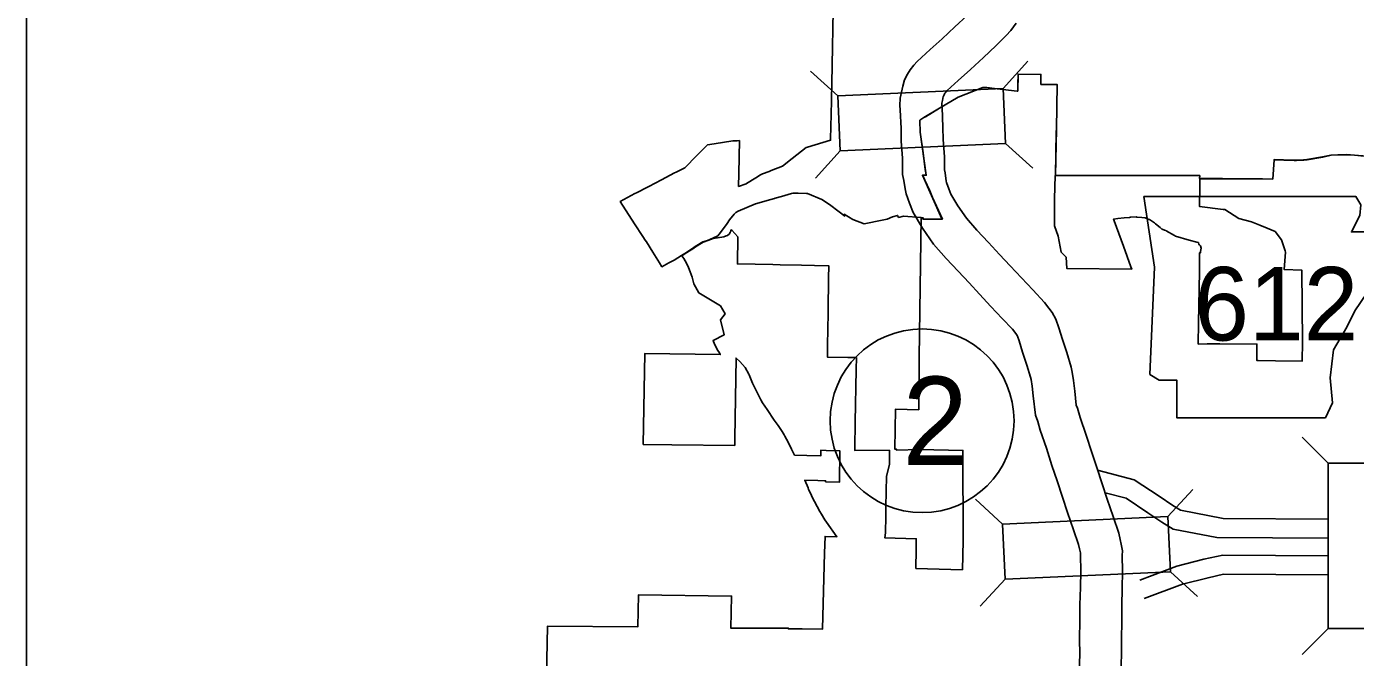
# Model space of a CAD drawing. Extents: x 670147 to 673275, y 705573 to 707613.
# Drawn here: x 670257.2 to 670400.2, y 707052.8 to 707120.8 of the extents above; entities that cross this region are included whole.
import ezdxf

# ---------------------------------------------------------------- set-up
doc = ezdxf.new("R2010")
doc.units = 0
for name, color, linetype in [('10', 7, 'Continuous'), ('20', 7, 'Continuous'), ('21', 7, 'Continuous'), ('27', 7, 'Continuous'), ('6', 7, 'Continuous'), ('R_NoPlot', 7, 'Continuous')]:
    doc.layers.add(name, color=color, linetype=linetype)

msp = doc.modelspace()

# ---------------------------------------------------------------- linework, layer by layer
at = {"layer": '10'}
for points in [[(670358.43, 707121.97), (670357.13, 707120.76), (670355.75, 707119.48), (670354.47, 707118.33), (670353.05, 707117.03), (670352.7, 707116.62), (670352.32, 707116.15), (670352.04, 707115.65), (670351.71, 707115.07), (670351.51, 707114.36), (670351.37, 707113.74), (670351.25, 707113.08), (670351.2, 707112.3), (670351.24, 707111.82), (670351.34, 707109.8), (670351.35, 707108.43), (670351.49, 707106.6), (670351.5, 707104.84), (670351.64, 707104.21), (670351.78, 707103.32), (670351.89, 707102.78), (670352.24, 707101.75), (670352.64, 707100.76), (670353.63, 707099.06), (670354.81, 707097.36), (670356.17, 707095.81), (670357.47, 707094.44), (670358.65, 707093.17), (670359.79, 707091.96), (670361.01, 707090.64), (670362.23, 707089.35), (670363.32, 707088.18), (670363.68, 707087.71), (670363.84, 707087.5), (670363.88, 707087.42), (670364.04, 707086.94), (670364.42, 707085.72), (670364.87, 707084.3), (670365.27, 707083.03), (670365.32, 707082.77), (670365.44, 707082.04), (670365.55, 707081.02), (670365.79, 707078.91), (670366.05, 707078.24), (670366.31, 707077.32), (670366.99, 707075.35), (670367.57, 707073.49), (670368.12, 707071.86), (670368.71, 707070.09), (670369.25, 707068.45), (670369.89, 707066.57), (670370.43, 707064.97), (670370.54, 707064.51), (670370.63, 707064.1), (670370.65, 707063.99), (670370.65, 707063.85), (670370.68, 707062.13), (670370.63, 707060.37), (670370.59, 707058.47), (670370.59, 707056.76), (670370.55, 707054.84), (670370.56, 707053.15), (670370.5, 707051.34)], [(670363.71, 707121.15), (670363.16, 707120.38), (670362.66, 707119.83), (670361.55, 707118.73), (670360.19, 707117.47), (670358.79, 707116.16), (670357.49, 707115), (670356.31, 707113.91), (670356.15, 707113.72), (670356.06, 707113.61), (670355.97, 707113.45), (670355.89, 707113.31), (670355.88, 707113.27), (670355.78, 707112.84), (670355.73, 707112.54), (670355.71, 707112.36), (670355.74, 707112.12), (670355.83, 707109.93), (670355.85, 707108.63), (670355.99, 707106.77), (670356, 707105.35), (670356.07, 707105.05), (670356.2, 707104.14), (670356.24, 707103.98), (670356.46, 707103.31), (670356.7, 707102.74), (670357.43, 707101.47), (670358.36, 707100.14), (670359.49, 707098.84), (670360.74, 707097.52), (670361.93, 707096.24), (670363.08, 707095.03), (670364.3, 707093.71), (670365.51, 707092.43), (670366.76, 707091.08), (670367.25, 707090.44), (670367.6, 707089.99), (670368.01, 707089.26), (670368.33, 707088.33), (670368.71, 707087.06), (670369.16, 707085.66), (670369.64, 707084.11), (670369.75, 707083.56), (670369.9, 707082.67), (670370.03, 707081.52), (670370.19, 707080), (670370.32, 707079.68), (670370.61, 707078.66), (670371.26, 707076.76), (670371.85, 707074.89), (670372.39, 707073.28), (670372.98, 707071.51), (670373.52, 707069.88), (670374.15, 707068.01), (670374.76, 707066.22), (670374.92, 707065.54), (670375.04, 707065.02), (670375.17, 707064.32), (670375.15, 707063.8), (670375.18, 707062.1), (670375.13, 707060.25), (670375.09, 707058.43), (670375.09, 707056.72), (670375.05, 707054.8), (670375.06, 707053.09), (670375, 707051.24)], [(670372.48, 707073.01), (670376.44, 707071.96), (670379.12, 707070.2), (670380.59, 707069.18), (670381.42, 707068.67), (670385.99, 707067.78)], [(670373.29, 707070.57), (670375.55, 707069.97), (670377.91, 707068.41), (670379.41, 707067.38), (670380.62, 707066.63), (670385.31, 707065.73)], [(670385.99, 707067.78), (670397.3, 707067.72)], [(670385.31, 707065.73), (670397.3, 707065.66)], [(670377.02, 707061.16), (670381.02, 707062.65), (670383.92, 707063.39), (670385.97, 707063.85)], [(670385.97, 707063.85), (670397.3, 707063.78)], [(670377.49, 707059.16), (670381.63, 707060.71), (670384.39, 707061.41), (670386.05, 707061.78)], [(670386.05, 707061.78), (670397.3, 707061.72)]]:
    msp.add_lwpolyline(points, dxfattribs=at)
at = {"layer": '20'}
for p, q in [((670362.31, 707114.13), (670364.98, 707117.06)), ((670344.51, 707113.33), (670341.59, 707116)), ((670362.58, 707108.2), (670365.5, 707105.53)), ((670344.78, 707107.39), (670342.11, 707104.47)), ((670397.31, 707073.76), (670394.51, 707076.57)), ((670380.06, 707067.99), (670382.73, 707070.92)), ((670362.26, 707067.19), (670359.34, 707069.86)), ((670380.33, 707062.06), (670383.25, 707059.39)), ((670362.53, 707061.25), (670359.86, 707058.33)), ((670397.3, 707055.94), (670394.5, 707053.14))]:
    msp.add_line(p, q, dxfattribs=at)
for points in [[(670362.31, 707114.13), (670344.51, 707113.33), (670344.78, 707107.39), (670362.58, 707108.2)], [(670397.31, 707073.76), (670397.3, 707055.94), (670403.24, 707055.94), (670403.25, 707073.76)], [(670380.06, 707067.99), (670362.26, 707067.19), (670362.53, 707061.25), (670380.33, 707062.06)]]:
    msp.add_lwpolyline(points, close=True, dxfattribs=at)
at = {"layer": '21'}
msp.add_lwpolyline([(670377.48, 707102.48), (670378.62, 707094.86), (670378.11, 707083.32), (670379.13, 707082.68), (670381.03, 707082.68), (670381.03, 707078.62), (670397.02, 707078.62), (670397.78, 707080.27), (670397.52, 707082.94), (670397.9, 707085.98), (670399.3, 707088.39), (670400.19, 707090.17), (670401.46, 707092.07), (670402.22, 707094.1), (670402.85, 707095.75), (670403.99, 707097.15), (670404.25, 707098.04), (670403.74, 707098.67), (670399.81, 707098.67), (670400.7, 707100.45), (670400.82, 707101.59), (670400.3, 707102.47)], close=True, dxfattribs=at)
at = {"layer": '27'}
msp.add_circle((670353.6, 707078.32), 9.9, dxfattribs=at)
at = {"layer": '6'}
for points in [[(670324.03, 707103.49), (670324.19, 707103.58), (670325.56, 707104.29), (670326.96, 707105.02), (670327.12, 707105.11), (670328.06, 707105.59), (670329.36, 707106.9), (670330.51, 707108.05), (670331.2, 707108.16), (670333.23, 707108.48), (670333.7, 707108.5), (670333.93, 707108.51), (670333.86, 707104.97), (670333.84, 707103.57), (670334.66, 707103.85), (670334.68, 707103.87), (670335.71, 707104.51), (670336.19, 707104.82), (670336.42, 707104.92), (670337.12, 707105.18), (670337.36, 707105.28), (670338.57, 707105.76), (670339.6, 707106.58), (670341.13, 707107.77), (670341.26, 707107.81), (670343.75, 707108.55), (670343.78, 707110.12), (670343.8, 707111.23), (670343.87, 707114.65), (670344.07, 707124.53)], [(670401.46, 707106.82), (670400.13, 707106.94), (670399.69, 707106.97), (670399.23, 707107), (670398.34, 707106.99), (670397.6, 707106.94), (670396.69, 707106.75), (670395.02, 707106.47), (670394.67, 707106.43), (670393.87, 707106.39), (670393.63, 707106.39), (670392.51, 707106.43), (670391.48, 707106.47), (670391.49, 707106.45), (670391.42, 707105.41), (670391.35, 707104.37), (670389.71, 707104.39), (670389.58, 707104.4), (670385.94, 707104.41), (670383.47, 707104.41), (670383.48, 707104.74), (670380.32, 707104.74), (670379.87, 707104.74), (670378.62, 707104.74), (670378.48, 707104.74), (670376.93, 707104.74), (670376.81, 707104.74), (670373.67, 707104.75), (670373.54, 707104.75), (670368.06, 707104.75), (670367.98, 707104.75), (670367.94, 707104.75), (670368.05, 707109.73), (670368.13, 707114.56), (670366.39, 707114.57), (670366.38, 707115.64), (670363.92, 707115.68), (670363.89, 707113.84), (670363.82, 707113.85), (670361.68, 707114.09), (670360.56, 707114.22), (670360.14, 707114.24), (670357.48, 707113.17), (670355.47, 707112.01), (670353.79, 707110.98), (670353.35, 707110.7), (670353.35, 707110.62), (670353.4, 707109.42), (670354.05, 707104.77), (670354.03, 707104.77), (670353.63, 707104.77), (670355.72, 707100.08), (670353.69, 707100.06), (670353.69, 707100.2), (670353.48, 707100.21), (670351.58, 707100.35), (670351.06, 707100.23), (670350.95, 707100.44), (670350.41, 707100.28), (670349.82, 707100.06), (670349.29, 707099.92), (670349.28, 707099.92), (670347.37, 707099.55), (670346.13, 707100), (670345.19, 707100.57), (670345.27, 707100.49), (670345.27, 707100.38), (670344.66, 707100.84), (670343.62, 707101.64), (670342.79, 707102.16), (670341.25, 707102.81), (670341.16, 707102.82), (670340.26, 707102.85), (670339.85, 707102.85), (670339.71, 707102.85), (670339.52, 707102.8), (670338.47, 707102.5), (670337.78, 707102.3), (670337.71, 707102.28), (670337.3, 707102.16), (670335.65, 707101.7), (670333.79, 707100.89), (670333.56, 707100.75), (670333.38, 707100.59), (670332.86, 707099.96), (670332.62, 707099.57), (670331.9, 707098.59), (670331.62, 707098.24), (670331.07, 707097.98), (670330.48, 707097.75), (670330.01, 707097.59), (670329.18, 707097.08), (670328.89, 707096.87), (670328.06, 707096.35), (670327.71, 707096.11), (670326.92, 707095.63), (670326.34, 707095.34), (670325.59, 707094.92), (670325.33, 707095.35), (670324.79, 707096.21), (670324.62, 707096.47), (670323.92, 707097.59), (670323.8, 707097.78), (670323.53, 707098.17), (670322.65, 707099.54), (670321.11, 707101.93), (670322.69, 707102.79), (670322.85, 707102.88), (670324.03, 707103.49)], [(670391.61, 707098.71), (670392.27, 707097.81), (670392.68, 707096.62), (670392.71, 707096.5), (670392.58, 707094.61), (670394.47, 707094.56), (670394.55, 707086.82), (670394.51, 707084.75), (670391.63, 707084.79), (670389.78, 707084.82), (670389.63, 707084.81), (670389.63, 707086.58), (670385.64, 707086.61), (670384.89, 707086.61), (670384.28, 707086.62), (670383.32, 707086.59), (670383.36, 707088.88), (670383.45, 707094.42), (670383.46, 707094.58), (670383.45, 707096.41), (670383.56, 707096.4), (670383.58, 707096.55), (670383.62, 707096.92), (670383.57, 707097.18), (670383.46, 707097.29), (670383.37, 707097.33), (670383.34, 707097.52), (670383.17, 707097.58), (670382.35, 707097.77), (670380.87, 707098.2), (670380.75, 707098.27), (670379.87, 707098.8), (670379.85, 707098.81), (670379.68, 707098.84), (670379.43, 707098.96), (670379.41, 707098.97), (670379.22, 707099.13), (670378.71, 707099.55), (670378.61, 707099.64), (670378.5, 707099.73), (670378.06, 707100), (670378.05, 707100), (670377.93, 707100.05), (670377.6, 707100.17), (670377.26, 707100.21), (670376.7, 707100.27), (670376.63, 707100.28), (670376.04, 707100.24), (670375.93, 707100.23), (670375.36, 707100.18), (670375.35, 707100.18), (670374.67, 707100.11), (670374.2, 707100.05), (670374.27, 707099.87), (670375.27, 707097.14), (670376.06, 707094.92), (670376.16, 707094.64), (670369.19, 707094.71), (670369.1, 707095.95), (670368.58, 707096.5), (670368.24, 707098.2), (670367.86, 707099.33), (670367.85, 707102.23), (670367.92, 707104.74), (670367.93, 707104.74), (670368.05, 707104.74), (670368.06, 707104.74), (670368.06, 707104.75), (670367.94, 707104.75), (670367.94, 707104.75), (670368.04, 707109.47), (670368.04, 707109.5), (670368.05, 707109.73), (670368.13, 707114.56), (670368.06, 707114.56), (670366.39, 707114.57), (670366.39, 707114.61), (670366.38, 707115.64), (670366.3, 707115.64), (670363.92, 707115.68), (670363.91, 707114.58), (670363.89, 707113.84), (670363.82, 707113.85), (670361.68, 707114.09), (670360.56, 707114.22), (670360.23, 707114.23), (670360.14, 707114.24), (670357.48, 707113.17), (670355.47, 707112.01), (670353.98, 707111.07), (670353.79, 707110.98), (670353.35, 707110.7), (670353.35, 707110.62), (670353.4, 707109.42), (670353.72, 707107.2), (670353.94, 707105.38), (670354, 707105.05), (670354.05, 707104.77), (670354.03, 707104.77), (670353.87, 707104.77)], [(670401.49, 707106.8), (670400.16, 707106.93), (670399.72, 707106.96), (670399.26, 707106.98), (670398.37, 707106.97), (670397.63, 707106.93), (670396.72, 707106.74), (670395.05, 707106.45), (670394.7, 707106.41), (670393.91, 707106.38), (670393.66, 707106.37), (670392.54, 707106.41), (670391.49, 707106.45), (670391.35, 707104.37), (670390.25, 707104.38), (670390.04, 707104.39), (670389.75, 707104.39), (670389.62, 707104.39), (670385.97, 707104.39), (670383.5, 707104.4), (670383.49, 707103.95), (670383.49, 707103.87), (670383.49, 707103.71), (670383.44, 707101.41), (670386.02, 707101.1), (670386.2, 707101.08), (670387.7, 707100.1), (670389.06, 707099.75), (670389.95, 707099.4), (670390.75, 707099.08), (670391.61, 707098.71)], [(670353.87, 707104.77), (670353.67, 707104.77), (670353.67, 707104.76), (670353.66, 707104.76), (670353.89, 707104.25), (670354.42, 707103.08), (670354.73, 707102.39), (670355.78, 707100.06), (670353.72, 707100.05), (670353.72, 707100.18), (670353.51, 707100.2), (670353.29, 707085.18), (670353.28, 707083.19), (670353.23, 707079.51), (670350.73, 707079.56), (670350.66, 707075.26), (670350.83, 707075.26), (670350.83, 707075.16), (670353.31, 707075.21), (670357.99, 707075.12), (670358, 707065.4), (670357.93, 707062.26), (670352.93, 707062.41), (670352.95, 707064.45), (670352.97, 707065.53), (670352.96, 707065.61), (670349.6, 707065.69), (670349.64, 707066.24), (670349.68, 707068.04), (670349.69, 707068.32), (670349.7, 707069.03), (670349.77, 707072.36), (670350.08, 707073.59), (670350.08, 707075.14), (670346.34, 707075.12), (670346.34, 707075.38), (670346.38, 707078.16), (670346.49, 707083.85), (670346.52, 707085.12), (670345.59, 707085.14), (670343.41, 707085.19), (670343.42, 707085.8), (670343.46, 707088.89), (670343.47, 707089.22), (670343.5, 707091.34), (670343.52, 707092.54), (670343.53, 707093.7), (670343.53, 707093.8), (670343.55, 707094.92), (670343.55, 707095.02), (670342.01, 707095.05), (670340.63, 707095.08), (670338.32, 707095.12), (670337.53, 707095.14), (670333.72, 707095.22), (670333.77, 707098.13), (670333.11, 707098.84), (670333.01, 707098.89), (670332.99, 707098.72), (670332.94, 707098.63), (670332.85, 707098.46), (670332.65, 707098.29), (670332.51, 707098.24), (670332.26, 707098.15), (670332.02, 707098.09), (670331.77, 707098.05), (670331.1, 707097.97), (670330.52, 707097.74), (670330.04, 707097.58), (670329.21, 707097.06), (670328.92, 707096.85), (670328.09, 707096.34), (670327.74, 707096.09), (670327.94, 707095.8), (670328.24, 707095.3), (670328.46, 707094.83), (670328.63, 707094.37), (670328.83, 707093.78), (670329.01, 707093.09), (670329.57, 707092.09), (670331.89, 707090.71), (670332.39, 707089.84), (670331.89, 707089.19), (670332.28, 707087.57), (670331.09, 707086.98), (670331.26, 707086.58), (670331.45, 707086.18), (670331.57, 707085.94), (670331.73, 707085.73), (670331.78, 707085.64), (670331.86, 707085.46), (670323.75, 707085.57), (670323.58, 707075.77), (670326.67, 707075.74), (670333.43, 707075.67), (670333.44, 707076.41), (670333.58, 707085.07), (670333.99, 707084.69), (670334.54, 707084.07), (670334.94, 707083.34)], [(670334.94, 707083.34), (670334.98, 707083.26), (670335.06, 707083.1), (670335.34, 707082.36), (670336.15, 707080.73), (670336.25, 707080.57), (670336.4, 707080.24), (670336.91, 707079.54), (670337.66, 707078.37), (670338.09, 707077.82), (670338.53, 707077.15), (670338.73, 707076.8), (670338.81, 707076.66), (670339.17, 707076.02), (670339.53, 707075.26), (670339.87, 707074.62), (670341.17, 707074.57), (670342.68, 707074.53), (670342.71, 707075.17), (670343.26, 707075.13), (670344.74, 707075.09), (670344.72, 707071.72), (670343.21, 707071.75), (670343.21, 707071.85), (670342.36, 707071.88), (670340.97, 707071.91), (670341.32, 707071.11), (670341.37, 707070.92), (670341.58, 707070.53), (670341.8, 707070.01), (670342.03, 707069.61), (670342.57, 707068.56), (670342.77, 707068.24), (670343.11, 707067.64), (670343.32, 707067.39), (670344.43, 707065.83), (670343.15, 707065.85), (670343.08, 707064.04), (670342.92, 707057.25), (670342.89, 707055.87), (670340.69, 707055.89), (670339.21, 707055.9), (670339.2, 707055.99), (670333.02, 707055.97), (670333.09, 707059.43), (670323.08, 707059.57), (670322.98, 707056.11), (670313.28, 707056.2), (670313.14, 707048.97)]]:
    msp.add_lwpolyline(points, dxfattribs=at)
at = {"layer": 'R_NoPlot'}
msp.add_lwpolyline([(670257.19, 707521.73), (670842.89, 707521.73), (670842.89, 706992.57), (670257.19, 706992.57)], close=True, dxfattribs=at)

# ---------------------------------------------------------------- texts
at = {"layer": '21'}
msp.add_text('612', height=7.92, dxfattribs=at).set_placement((670382.89, 707086.97))
at = {"layer": '27'}
msp.add_text('2', height=9.5, dxfattribs=at).set_placement((670351.48, 707073.57))

doc.saveas('drawing.dxf')
